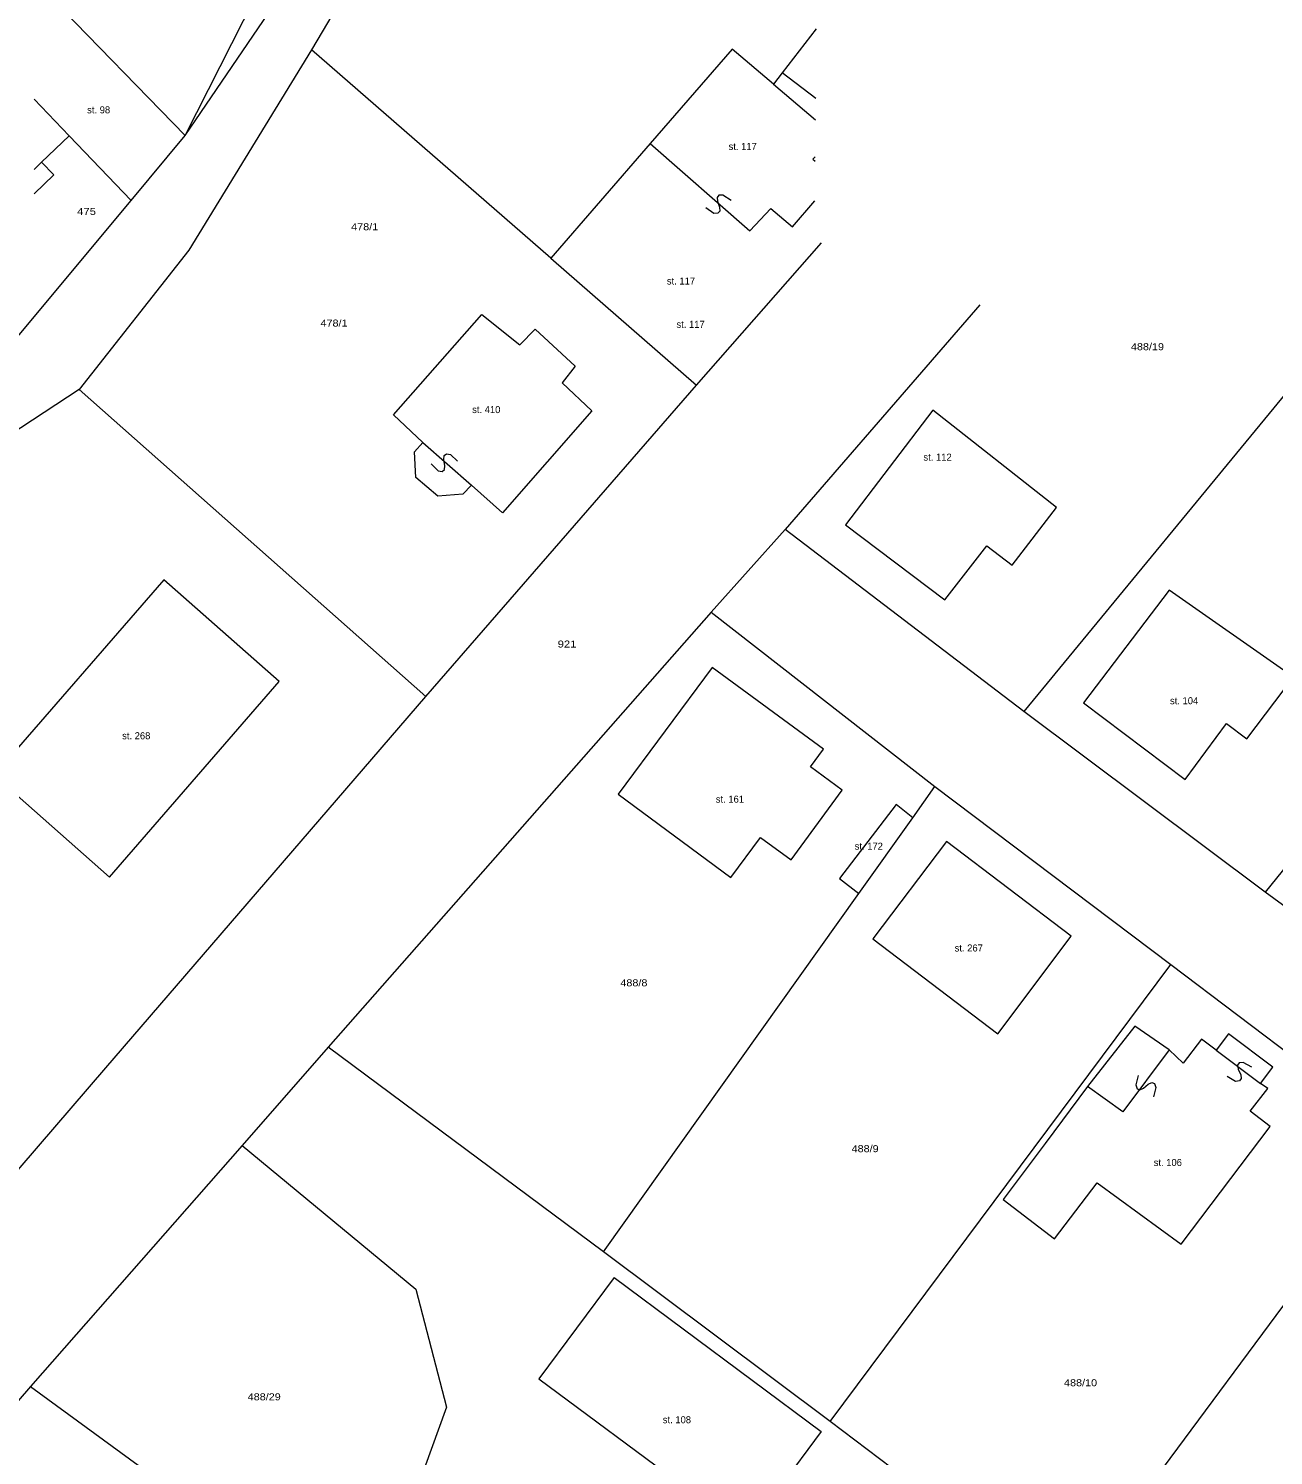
# Model space of a CAD drawing. Extents: x -694702 to -694000, y -1089746 to -1089192.
# Drawn here: x -694637.4 to -694548.9, y -1089487.5 to -1089386.1 of the extents above; entities that cross this region are included whole.
import ezdxf

# ---------------------------------------------------------------- set-up
doc = ezdxf.new("R2010")
doc.units = 0
doc.header["$LTSCALE"] = 0.2
doc.layers.add('50', color=7, linetype='Continuous', lineweight=13)
doc.layers.add('52', color=7, linetype='Continuous', lineweight=13)

msp = doc.modelspace()

# ---------------------------------------------------------------- linework, layer by layer
at = {"layer": '50'}
for p, q in [((-694626.27, -1089393.68), (-694607.67, -1089366.38)), ((-694606.14, -1089368.76), (-694617.27, -1089387.58)), ((-694626.27, -1089393.68), (-694637.01, -1089382.62)), ((-694626.27, -1089393.68), (-694620.82, -1089382.95)), ((-694581.37, -1089386.09), (-694583.8, -1089389.22)), ((-694600.26, -1089402.4), (-694617.27, -1089387.58)), ((-694581.41, -1089391.04), (-694583.8, -1089389.22)), ((-694584.42, -1089390.02), (-694581.43, -1089392.55)), ((-694634.52, -1089393.69), (-694637.01, -1089391.09)), ((-694630.11, -1089398.29), (-694626.27, -1089393.68)), ((-694593.18, -1089394.25), (-694586.1, -1089400.44)), ((-694637.01, -1089396.08), (-694636.49, -1089395.58)), ((-694581.45, -1089395.18), (-694581.61, -1089395.36)), ((-694581.61, -1089395.36), (-694581.46, -1089395.49)), ((-694640.89, -1089411.2), (-694630.11, -1089398.29)), ((-694583.07, -1089400.16), (-694581.48, -1089398.31)), ((-694584.6, -1089398.86), (-694586.1, -1089400.44)), ((-694584.6, -1089398.86), (-694583.07, -1089400.16)), ((-694589.9, -1089411.42), (-694581.01, -1089401.31)), ((-694600.26, -1089402.4), (-694589.9, -1089411.42)), ((-694569.73, -1089405.71), (-694583.59, -1089421.69)), ((-694542.8, -1089405.71), (-694566.61, -1089434.62)), ((-694633.81, -1089411.74), (-694643.75, -1089418.24)), ((-694633.81, -1089411.74), (-694609.14, -1089433.55)), ((-694609.14, -1089433.55), (-694589.9, -1089411.42)), ((-694523.11, -1089414.76), (-694549.44, -1089447.48)), ((-694609.37, -1089415.51), (-694605.9, -1089418.53)), ((-694583.59, -1089421.69), (-694588.84, -1089427.56)), ((-694566.61, -1089434.62), (-694583.59, -1089421.69)), ((-694588.84, -1089427.56), (-694572.93, -1089439.96)), ((-694549.44, -1089447.48), (-694566.61, -1089434.62)), ((-694574.51, -1089442.18), (-694572.93, -1089439.96)), ((-694572.93, -1089439.96), (-694556.16, -1089452.62)), ((-694532.52, -1089459.92), (-694549.44, -1089447.48)), ((-694596.5, -1089473.04), (-694578.35, -1089447.57)), ((-694580.39, -1089485.1), (-694556.16, -1089452.62)), ((-694556.16, -1089452.62), (-694539.5, -1089465.2)), ((-694548.9, -1089459.91), (-694552.04, -1089457.54)), ((-694596.5, -1089473.04), (-694616.09, -1089458.49)), ((-694556.26, -1089458.69), (-694559.56, -1089463.08)), ((-694552.92, -1089458.71), (-694549.78, -1089461.07)), ((-694559.56, -1089463.08), (-694562.07, -1089461.29)), ((-694622.21, -1089465.48), (-694637.28, -1089482.61)), ((-694563.62, -1089497.74), (-694539.5, -1089465.2)), ((-694568.07, -1089469.33), (-694564.42, -1089472.11)), ((-694580.39, -1089485.1), (-694596.5, -1089473.04)), ((-694595.75, -1089474.87), (-694601.1, -1089482.07)), ((-694595.75, -1089474.87), (-694581.02, -1089485.81)), ((-694637.28, -1089482.61), (-694650.77, -1089498.36)), ((-694637.28, -1089482.61), (-694613.45, -1089500)), ((-694601.1, -1089482.07), (-694586.36, -1089493)), ((-694581.02, -1089485.81), (-694586.36, -1089493)), ((-694563.62, -1089497.74), (-694580.39, -1089485.1))]:
    msp.add_line(p, q, dxfattribs=at)
for points in [[(-694617.27, -1089387.58), (-694626, -1089401.82), (-694633.81, -1089411.74)], [(-694583.8, -1089389.22), (-694584.42, -1089390.02), (-694587.35, -1089387.54), (-694593.18, -1089394.25), (-694600.26, -1089402.4)], [(-694637.01, -1089397.81), (-694635.62, -1089396.48), (-694636.49, -1089395.58), (-694634.52, -1089393.69), (-694630.11, -1089398.29)], [(-694588.84, -1089427.56), (-694616.09, -1089458.49), (-694622.21, -1089465.48)], [(-694650.22, -1089481.22), (-694631.91, -1089459.97), (-694609.14, -1089433.55)], [(-694552.04, -1089457.54), (-694552.92, -1089458.71), (-694553.96, -1089457.92), (-694555.27, -1089459.63), (-694556.26, -1089458.69), (-694558.71, -1089457.01), (-694562.07, -1089461.29), (-694565.09, -1089465.34), (-694568.07, -1089469.33)], [(-694564.42, -1089472.11), (-694561.4, -1089468.14), (-694555.42, -1089472.51), (-694549.08, -1089464.14), (-694550.51, -1089463.05), (-694549.24, -1089461.42), (-694549.78, -1089461.07), (-694548.9, -1089459.91)], [(-694622.21, -1089465.48), (-694609.86, -1089475.7), (-694607.68, -1089484.09), (-694613.45, -1089500)]]:
    msp.add_lwpolyline(points, dxfattribs=at)
for points in [[(-694598.53, -1089410.08), (-694599.44, -1089411.27), (-694597.35, -1089413.26), (-694603.69, -1089420.49), (-694605.9, -1089418.53), (-694606.51, -1089419.17), (-694608.3, -1089419.31), (-694609.85, -1089417.99), (-694609.95, -1089416.16), (-694609.37, -1089415.51), (-694611.44, -1089413.54), (-694605.16, -1089406.39), (-694602.45, -1089408.55), (-694601.37, -1089407.45)], [(-694564.29, -1089420.13), (-694573.08, -1089413.21), (-694579.29, -1089421.36), (-694572.22, -1089426.69), (-694569.25, -1089422.84), (-694567.43, -1089424.22)], [(-694631.65, -1089446.4), (-694619.57, -1089432.5), (-694627.78, -1089425.26), (-694639.88, -1089439.15)], [(-694552.18, -1089435.48), (-694550.74, -1089436.56), (-694547.43, -1089432.18), (-694556.26, -1089426.01), (-694562.37, -1089434.01), (-694555.14, -1089439.45)], [(-694587.45, -1089446.44), (-694585.35, -1089443.58), (-694583.17, -1089445.17), (-694579.53, -1089440.22), (-694581.79, -1089438.56), (-694580.87, -1089437.31), (-694588.78, -1089431.5), (-694595.46, -1089440.5)], [(-694574.51, -1089442.18), (-694575.69, -1089441.23), (-694579.71, -1089446.5), (-694578.35, -1089447.57)], [(-694568.45, -1089457.55), (-694563.24, -1089450.59), (-694572.1, -1089443.87), (-694577.35, -1089450.79)]]:
    msp.add_lwpolyline(points, close=True, dxfattribs=at)
at = {"layer": '52'}
for points in [[(-694587.429, -1089398.303), (-694588.01, -1089397.914), (-694588.296, -1089397.923), (-694588.434, -1089398.07), (-694588.411, -1089398.354), (-694588.249, -1089398.77), (-694588.234, -1089399.047), (-694588.364, -1089399.201), (-694588.655, -1089399.218), (-694589.232, -1089398.82)], [(-694608.769, -1089417.022), (-694608.267, -1089417.51), (-694607.985, -1089417.552), (-694607.822, -1089417.432), (-694607.794, -1089417.149), (-694607.878, -1089416.711), (-694607.843, -1089416.435), (-694607.688, -1089416.308), (-694607.398, -1089416.343), (-694606.903, -1089416.838)], [(-694550.39, -1089459.92), (-694551.01, -1089459.58), (-694551.29, -1089459.61), (-694551.42, -1089459.77), (-694551.37, -1089460.05), (-694551.18, -1089460.45), (-694551.14, -1089460.72), (-694551.26, -1089460.89), (-694551.55, -1089460.93), (-694552.15, -1089460.58)], [(-694558.48, -1089460.5), (-694558.65, -1089461.18), (-694558.55, -1089461.45), (-694558.36, -1089461.53), (-694558.1, -1089461.41), (-694557.76, -1089461.12), (-694557.51, -1089461.01), (-694557.32, -1089461.08), (-694557.21, -1089461.35), (-694557.39, -1089462.03)]]:
    msp.add_lwpolyline(points, dxfattribs=at)

# ---------------------------------------------------------------- texts
for s, p in [('st. 98', (-694633.24, -1089392.1)), ('st. 117', (-694587.61, -1089394.7)), ('st. 117', (-694592, -1089404.27)), ('st. 117', (-694591.32, -1089407.35)), ('st. 410', (-694605.85, -1089413.41)), ('st. 112', (-694573.75, -1089416.79)), ('st. 104', (-694556.21, -1089434.11)), ('st. 268', (-694630.75, -1089436.6)), ('st. 161', (-694588.52, -1089441.11)), ('st. 172', (-694578.64, -1089444.45)), ('st. 267', (-694571.53, -1089451.69)), ('st. 106', (-694557.37, -1089466.94)), ('st. 108', (-694592.29, -1089485.23))]:
    msp.add_text(s, height=0.5, dxfattribs=at).set_placement(p)
for s, width, p in [('475', 1.2, (-694633.95, -1089399.32)), ('478/1', 1.15, (-694614.46, -1089400.41)), ('478/1', 1.15, (-694616.64, -1089407.26)), ('488/19', 1.15, (-694558.99, -1089408.94)), ('921', 1.2, (-694599.77, -1089430.08)), ('488/8', 1.15, (-694595.31, -1089454.17)), ('488/9', 1.15, (-694578.86, -1089465.96)), ('488/10', 1.15, (-694563.75, -1089482.6)), ('488/29', 1.15, (-694621.82, -1089483.6))]:
    msp.add_text(s, height=0.5, dxfattribs=dict(at, width=width)).set_placement(p)

doc.saveas('drawing.dxf')
